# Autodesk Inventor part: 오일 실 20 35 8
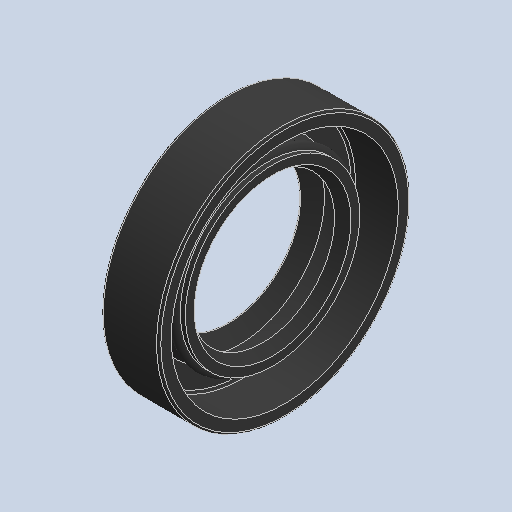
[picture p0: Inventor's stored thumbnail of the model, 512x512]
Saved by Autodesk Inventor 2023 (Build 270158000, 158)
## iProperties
Created: 2024-09
Part Number: 오일 실 20 35 8
Material: 고무
Description: 오일-실
Document SubType Name: Modeling
Designer: home
Density: 0.93 g/cm^3
Appearance: 기본값
Author: jhkim
Sending System: Autodesk Inventor 2025
Preprocessor: ST-DEVELOPER v20
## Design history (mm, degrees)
feature "Solid1"
node "솔리드1"
